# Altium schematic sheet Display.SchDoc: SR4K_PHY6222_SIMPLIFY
size A4; Revision: V1.2; SheetNumber: 3; SheetTotal: 5
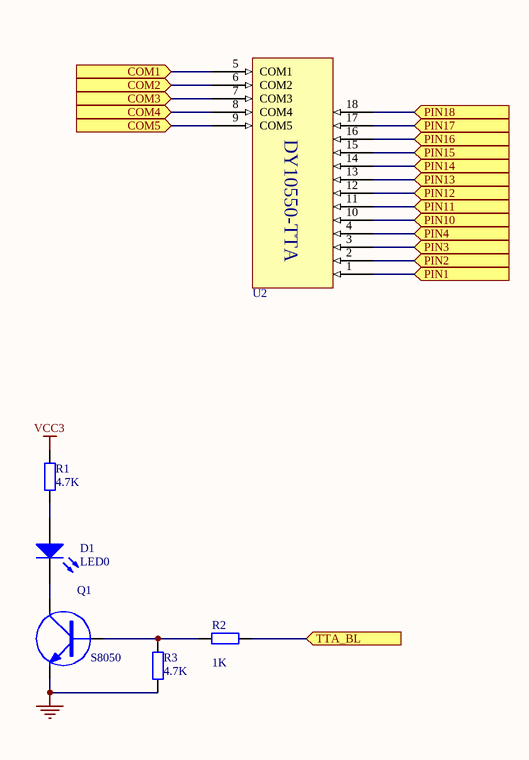
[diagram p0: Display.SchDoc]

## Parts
D1  LED0
Q1  S8050
R1  value 4.7K  (hidden comment: Res2)
R2  value 1K  (hidden comment: Res2)
R3  value 4.7K  (hidden comment: 100K)
U2  DY10550-TTA_1  (value not drawn)

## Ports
COM1 (in), COM2 (in), COM3 (in), COM4 (in), COM5 (in), PIN1 (in), PIN2 (in), PIN3 (in), PIN4 (in), PIN10 (in), PIN11 (in), PIN12 (in), PIN13 (in), PIN14 (in), PIN15 (in), PIN16 (in), PIN17 (in), PIN18 (in), TTA_BL (in)

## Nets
GND: Q1.2(E) R3.1
VCC3: R1.2
COM1: U2.5(COM1) ; port COM1
COM2: U2.6(COM2) ; port COM2
COM3: U2.7(COM3) ; port COM3
COM4: U2.8(COM4) ; port COM4
COM5: U2.9(COM5) ; port COM5
PIN1: U2.1 ; port PIN1
PIN2: U2.2 ; port PIN2
PIN3: U2.3 ; port PIN3
PIN4: U2.4 ; port PIN4
PIN10: U2.10 ; port PIN10
PIN11: U2.11 ; port PIN11
PIN12: U2.12 ; port PIN12
PIN13: U2.13 ; port PIN13
PIN14: U2.14 ; port PIN14
PIN15: U2.15 ; port PIN15
PIN16: U2.16 ; port PIN16
PIN17: U2.17 ; port PIN17
PIN18: U2.18 ; port PIN18
TTA_BL: R2.2 ; port TTA_BL
NetD1_1: D1.1(A) R1.1
NetD1_2: D1.2(K) Q1.3(C)
NetQ1_1: Q1.1(B) R2.1 R3.2

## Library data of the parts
D1 = LED0: Typical INFRARED GaAs LED
Q1 = NPN: NPN Transistor
R1-R3 = Res2: Resistor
